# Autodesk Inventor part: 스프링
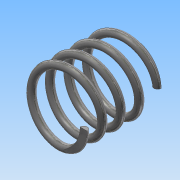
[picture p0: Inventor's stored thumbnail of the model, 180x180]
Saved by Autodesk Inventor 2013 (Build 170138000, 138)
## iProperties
Created: 2017-07
Part Number: 스프링
Material: 스테인리스강
Document SubType Name: Modeling
Designer: Administrator
Density: 8.08 g/cm^3
Mass: 5.31055 g
Surface Area: 13.3833 cm^2
Volume: 0.657246 cm^3
Author: Administrator
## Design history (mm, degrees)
sketch "스케치1"
  geometry: L1 (8.5, 0)-(0, 0); L2 (0, 0)-(0, 20.5); L3 (0, 20.5)-(8.5, 20.5); C1 r 1 at (8.5, 0); 1 further point
  constraints: 6 end point, 2 coincident, 1 centre point, 1 horizontal, 1 parallel, 1 perpendicular
  dimensions: "d0" = 8.5 distance of L1.start L1.end; "d2" = 20.5 distance of L1.end L2.end (derived); "d3" = 8.5 distance of L2.end L3.end; "d4" = 2 diameter of C1
feature "코일1" sketch "스케치1" pitch "d5" = 10; turns "d7" = 4; dims "d6" = 20.5 (= d2), "d8" = 0, angle "d9" = 90 deg, angle "d10" = 90 deg, "d11" = 0, "d12" = 0
sketch "스케치2"
  geometry: L1 (0, 11.573)-(20.5, 11.573); L2 (20.5, 11.573)-(20.5, -15.349); L3 (20.5, -15.349)-(0, -15.349); L4 (0, -15.349)-(0, 11.573); 1 further point
  constraints: 8 end point, 2 parallel, 1 horizontal, 1 perpendicular, 1 point on line
  dimensions: "d13" = 20.5 distance of L1.start L1.end (derived)
extrude "돌출2" sketch "스케치2" stored distance "d17" = 40; taper "d18" = 0 deg
node "솔리드1"
